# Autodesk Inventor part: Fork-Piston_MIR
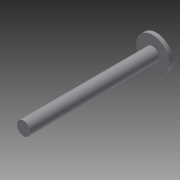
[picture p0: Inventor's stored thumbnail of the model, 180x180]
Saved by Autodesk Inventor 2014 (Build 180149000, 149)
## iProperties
Created: 2001-11
Part Number: Fork-Piston_MIR
Document SubType Name: Modeling
Designer: Autodesk, Inc.
Mass: 6.28409 g
Surface Area: 33.2778 cm^2
Volume: 6.28409 cm^3
Density: 1 g/cm^3
Material: Generic
Appearance: Default
Author: Autodesk, Inc.
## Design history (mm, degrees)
derived "Fork-Piston.ipt"
body "Solid1"
tag "TaggingFeature2"
feature "DerivedBody::Fork-Piston.ipt" dims "d0" = 10
